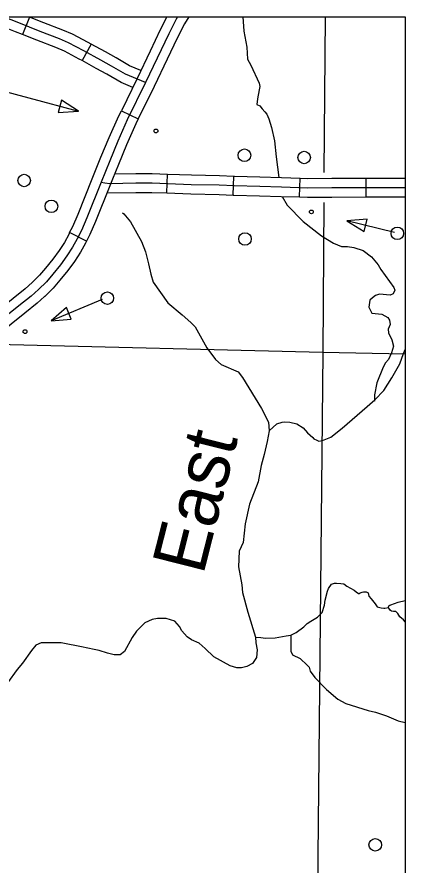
# Model space of a CAD drawing. Extents: x 1382482 to 1385815, y 1168351 to 1170484.
# Drawn here: x 1384816.3 to 1384939.9, y 1169309.6 to 1169579.7 of the extents above; entities that cross this region are included whole.
import ezdxf

# ---------------------------------------------------------------- set-up
doc = ezdxf.new("R2010")
doc.units = 0
for name, color, linetype in [('32', 7, 'Continuous'), ('35', 7, 'Continuous'), ('5', 7, 'Continuous'), ('57', 7, 'Continuous'), ('Default', 7, 'Continuous'), ('R_No Plot', 7, 'Continuous')]:
    doc.layers.add(name, color=color, linetype=linetype)

msp = doc.modelspace()

# ---------------------------------------------------------------- linework, layer by layer
at = {"layer": '32'}
for p, q in [((1384820.26, 1169579.68), (1384818.05, 1169574.1)), ((1384839.91, 1169571.05), (1384837.03, 1169565.79)), ((1384864.05, 1169523.66), (1384864.28, 1169529.65)), ((1384885.14, 1169522.99), (1384885.41, 1169528.99)), ((1384906.29, 1169522.37), (1384906.48, 1169528.36)), ((1384927.5, 1169522.38), (1384927.5, 1169528.38))]:
    msp.add_line(p, q, dxfattribs=at)
for points in [[(1384857.24, 1169558.81), (1384850.81, 1169561.48), (1384846.36, 1169564.05), (1384843.02, 1169565.93), (1384837.54, 1169568.93), (1384832.72, 1169571.48), (1384829.81, 1169572.72), (1384823.72, 1169575.08), (1384816.91, 1169577.78), (1384812.01, 1169579.7)], [(1384820.26, 1169579.68), (1384820.22, 1169579.7)], [(1384839.91, 1169571.05), (1384838.96, 1169571.57), (1384834.01, 1169574.19), (1384830.94, 1169575.5), (1384824.82, 1169577.87), (1384820.26, 1169579.68)], [(1384818.05, 1169574.1), (1384815.82, 1169574.99), (1384810.38, 1169577.11), (1384808.77, 1169577.69), (1384807.88, 1169577.95), (1384806.59, 1169578.16), (1384805.27, 1169578.23), (1384802.64, 1169578.4), (1384799.83, 1169578.53), (1384798.73, 1169578.56)], [(1384837.03, 1169565.79), (1384836.11, 1169566.29), (1384831.43, 1169568.77), (1384828.68, 1169569.94), (1384822.63, 1169572.29), (1384818.05, 1169574.1)], [(1384855.76, 1169562.67), (1384852.14, 1169564.17), (1384847.85, 1169566.65), (1384844.48, 1169568.56), (1384839.91, 1169571.05)], [(1384853.15, 1169557.26), (1384849.48, 1169558.78), (1384844.87, 1169561.44), (1384841.56, 1169563.31), (1384837.03, 1169565.79)], [(1384847.38, 1169529.73), (1384854.15, 1169529.84), (1384859.37, 1169529.84), (1384864.28, 1169529.65)], [(1384864.28, 1169529.65), (1384871.88, 1169529.37), (1384880.84, 1169529.19), (1384885.41, 1169528.99)], [(1384885.41, 1169528.99), (1384885.6, 1169528.98), (1384893.68, 1169528.77), (1384900.58, 1169528.55), (1384906.48, 1169528.36)], [(1384906.48, 1169528.36), (1384908.9, 1169528.29), (1384916.52, 1169528.36), (1384927.5, 1169528.38)], [(1384927.5, 1169528.38), (1384939.88, 1169528.39)], [(1384843.08, 1169527.07), (1384844.24, 1169526.84), (1384845.82, 1169526.71), (1384854.17, 1169526.84), (1384859.31, 1169526.84), (1384871.79, 1169526.37), (1384880.74, 1169526.2), (1384885.5, 1169525.98), (1384893.59, 1169525.77), (1384900.49, 1169525.55), (1384908.86, 1169525.29)], [(1384908.86, 1169525.29), (1384916.53, 1169525.36), (1384939.88, 1169525.39)], [(1384844.96, 1169523.7), (1384854.2, 1169523.84), (1384859.25, 1169523.84), (1384864.05, 1169523.66)], [(1384864.05, 1169523.66), (1384871.71, 1169523.37), (1384880.65, 1169523.2), (1384885.14, 1169522.99)], [(1384885.14, 1169522.99), (1384885.39, 1169522.98), (1384893.5, 1169522.77), (1384900.39, 1169522.55), (1384906.29, 1169522.37)], [(1384906.29, 1169522.37), (1384908.83, 1169522.29), (1384916.55, 1169522.36), (1384927.5, 1169522.38)], [(1384927.5, 1169522.38), (1384939.88, 1169522.39)]]:
    msp.add_lwpolyline(points, dxfattribs=at)
at = {"layer": '35'}
for points in [[(1384888.21, 1169579.7), (1384888.51, 1169575.15), (1384889.47, 1169570.08), (1384889.67, 1169566.29), (1384890.82, 1169564.37), (1384893.44, 1169558.6), (1384893.65, 1169557.56), (1384892.97, 1169554.23), (1384892.77, 1169552.76), (1384892.73, 1169551.77), (1384893.64, 1169551.43), (1384894.41, 1169550.44), (1384895.2, 1169549.45), (1384895.89, 1169548.73), (1384896.46, 1169547.28), (1384897.32, 1169544.51), (1384898.34, 1169540.28), (1384898.81, 1169535.12), (1384899.69, 1169528.58)], [(1384900.75, 1169522.54), (1384902.3, 1169519.79), (1384907.43, 1169514.59), (1384913.32, 1169509.96), (1384917.13, 1169507.64), (1384919.69, 1169506.64), (1384921.54, 1169506.6), (1384923.53, 1169506.26)], [(1384849.95, 1169517.34), (1384850.34, 1169517.01), (1384852.48, 1169514.44), (1384855.97, 1169508.19), (1384857.23, 1169504.88), (1384858.22, 1169501.09), (1384858.88, 1169497.77), (1384859.65, 1169495.22), (1384864.31, 1169488.62), (1384868.95, 1169484.88), (1384871.64, 1169482.44), (1384873, 1169480.97), (1384876.79, 1169474.32), (1384879.57, 1169470.62), (1384881.33, 1169468.99), (1384886.69, 1169466.67), (1384888.09, 1169464.92), (1384894.21, 1169455.05), (1384896.4, 1169450.66), (1384896.56, 1169447.95), (1384896, 1169444.49)], [(1384923.53, 1169506.26), (1384926.57, 1169505.31), (1384929.23, 1169503.35), (1384931.36, 1169500.81), (1384932.16, 1169499.33), (1384936.27, 1169493.57), (1384936.59, 1169492.65), (1384936.06, 1169491.56), (1384935.16, 1169491.09), (1384931.75, 1169491.47), (1384930.46, 1169491.04), (1384929.47, 1169490.22), (1384928.71, 1169489.47), (1384928.38, 1169487.29), (1384929.28, 1169485.39), (1384932.45, 1169485.02), (1384934.45, 1169484), (1384934.94, 1169483.16), (1384935.14, 1169481.8), (1384934.52, 1169480.32), (1384934.64, 1169479.12), (1384935.69, 1169476.93), (1384936.22, 1169474.85), (1384935.56, 1169472.69), (1384934.58, 1169470.64), (1384933.63, 1169469.56), (1384932.88, 1169468.19), (1384930.92, 1169463.22), (1384930.14, 1169459.34), (1384930.16, 1169457.38)], [(1384896.56, 1169447.95), (1384899.03, 1169450.11), (1384900.7, 1169450.64), (1384901.54, 1169450.8), (1384903.22, 1169450.64), (1384905.42, 1169450.11), (1384907.48, 1169448.89), (1384908.85, 1169447.3), (1384910.52, 1169445.77), (1384910.82, 1169445.39), (1384911.74, 1169444.94), (1384912.42, 1169444.63), (1384913.64, 1169444.78), (1384916.22, 1169445.93), (1384919.88, 1169448.74), (1384926.19, 1169454.22), (1384930.3, 1169457.8), (1384933.11, 1169460.77), (1384935.7, 1169464.8), (1384938.21, 1169469.29), (1384939.43, 1169472.56), (1384939.88, 1169473.81)], [(1384896, 1169444.49), (1384895, 1169440.37), (1384894.11, 1169436.89), (1384893.13, 1169431.61), (1384890.3, 1169424.54), (1384888.94, 1169418.26), (1384888.36, 1169412.33), (1384887.11, 1169409.59), (1384886.88, 1169404.57), (1384887.95, 1169398.87), (1384888.17, 1169396.39), (1384889.87, 1169390.17), (1384892.27, 1169382.24), (1384892.37, 1169380.35), (1384892.78, 1169378.19), (1384892.56, 1169375.71), (1384891.3, 1169373.8), (1384889.51, 1169372.85), (1384887.8, 1169372.39), (1384886.33, 1169372.43), (1384884.17, 1169373.11), (1384878.99, 1169375.92), (1384876.27, 1169378.56), (1384874.27, 1169380.27), (1384871.88, 1169381.36), (1384870.45, 1169382.35), (1384868.8, 1169384.18), (1384868.1, 1169385.61), (1384866.52, 1169387.29), (1384863.86, 1169388.16), (1384861.02, 1169388.18), (1384859.38, 1169387.81), (1384856.98, 1169386.77), (1384854.37, 1169384.07), (1384853, 1169382.04), (1384850.52, 1169377.58), (1384849.18, 1169376.53), (1384847.25, 1169376.61), (1384845.09, 1169377.06), (1384842.5, 1169377.97), (1384840.85, 1169378.25), (1384836.86, 1169379.08), (1384834.7, 1169379.5), (1384832.99, 1169379.9), (1384830.34, 1169380.41), (1384823.96, 1169380.41), (1384822.32, 1169379.7), (1384820.95, 1169377.99), (1384818.04, 1169373.94), (1384816.33, 1169371.94), (1384813.31, 1169367.67)], [(1384915.46, 1169397.68), (1384916.49, 1169399.1), (1384917.4, 1169399.44), (1384918.08, 1169399.44), (1384919.45, 1169399.27), (1384920.42, 1169399.15), (1384921.39, 1169398.47), (1384923.73, 1169397.21), (1384924.36, 1169396.64), (1384925.04, 1169396.13), (1384925.27, 1169396.13), (1384925.55, 1169396.36), (1384926.24, 1169396.53), (1384926.64, 1169396.64), (1384927.55, 1169396.64), (1384928.12, 1169396.3), (1384928.4, 1169395.28), (1384929.09, 1169394.42), (1384930.34, 1169392.77), (1384931.03, 1169391.85), (1384932.28, 1169391.57), (1384933.08, 1169391.45), (1384933.48, 1169391.45), (1384934.62, 1169391.68)], [(1384892.27, 1169382.24), (1384893.98, 1169382.07), (1384895.49, 1169381.84), (1384898.57, 1169382.02), (1384901.99, 1169382.59), (1384903.56, 1169382.87), (1384905.19, 1169383.73), (1384907.7, 1169385.5), (1384908.72, 1169386.52), (1384909.92, 1169387.26), (1384912.03, 1169388.58), (1384913.46, 1169390), (1384914.2, 1169392.4), (1384914.43, 1169394), (1384915.17, 1169396.85), (1384915.46, 1169397.68)], [(1384939.88, 1169387.12), (1384939.38, 1169387.76), (1384938.24, 1169388.68), (1384937.55, 1169389.76), (1384936.98, 1169390.33), (1384936.18, 1169390.39), (1384935.61, 1169390.44), (1384935.27, 1169390.73), (1384934.76, 1169391.41), (1384934.62, 1169391.68), (1384934.73, 1169392.14), (1384935.08, 1169392.38), (1384935.4, 1169392.49), (1384937.68, 1169393.34), (1384939.88, 1169393.91)], [(1384903.56, 1169382.87), (1384903.5, 1169381.73), (1384903.5, 1169379.33), (1384903.56, 1169377.73), (1384904.07, 1169376.59), (1384906.47, 1169375.39), (1384908.75, 1169373.23), (1384909.37, 1169372.6), (1384909.65, 1169371.35), (1384911.14, 1169369.36), (1384914.87, 1169365.55), (1384918.52, 1169362.5), (1384921.04, 1169361.12), (1384928.19, 1169358.85), (1384930.5, 1169358.3), (1384933.98, 1169357.17), (1384937.65, 1169355.56), (1384939.88, 1169354.98)]]:
    msp.add_lwpolyline(points, dxfattribs=at)
at = {"layer": '5'}
for points in [[(1384914.41, 1169579.7), (1384914.07, 1169530.19)], [(1384914, 1169520.62), (1384913.68, 1169472.9)], [(1384809.66, 1169475.5), (1384913.68, 1169472.9)], [(1384913.68, 1169472.9), (1384911.88, 1169290.87)], [(1384913.68, 1169472.9), (1384939.88, 1169472.42)]]:
    msp.add_lwpolyline(points, dxfattribs=at)
at = {"layer": '57'}
msp.add_lwpolyline([(1384804.15, 1169558.21), (1384835.89, 1169549.68)], dxfattribs=at)
msp.add_lwpolyline([(1384830.51, 1169553.24), (1384829.45, 1169549.3), (1384835.89, 1169549.68)], close=True, dxfattribs=at)
msp.add_circle((1384860.57, 1169543.4), 0.6, dxfattribs=at)
at = {"layer": 'Default'}
for p, q in [((1384849.54, 1169549.84), (1384854.93, 1169547.21)), ((1384838.42, 1169508.29), (1384833.07, 1169511.01)), ((1384838.42, 1169508.29), (1384838.42, 1169508.29))]:
    msp.add_line(p, q, dxfattribs=at)
for points in [[(1384867.43, 1169579.7), (1384867, 1169579.03), (1384864.61, 1169574.3), (1384857.24, 1169558.81)], [(1384863.98, 1169579.7), (1384861.92, 1169575.62), (1384858.69, 1169568.84)], [(1384870.99, 1169579.7), (1384869.61, 1169577.54), (1384867.3, 1169572.98), (1384864.11, 1169566.26)], [(1384858.69, 1169568.84), (1384854.54, 1169560.11), (1384849.54, 1169549.84)], [(1384864.11, 1169566.26), (1384859.95, 1169557.51), (1384854.93, 1169547.21)], [(1384857.24, 1169558.81), (1384851.44, 1169546.89), (1384848.46, 1169540.16), (1384845.82, 1169533.9), (1384843.08, 1169527.07), (1384838.58, 1169515.76), (1384836.8, 1169511.71), (1384835.43, 1169509.03), (1384833.99, 1169506.35), (1384832.2, 1169503.58), (1384830.11, 1169500.77), (1384827.68, 1169497.74), (1384825.66, 1169495.38), (1384823.15, 1169492.91), (1384820.81, 1169490.82), (1384816.93, 1169487.67), (1384808.12, 1169480.69)], [(1384841.12, 1169530.24), (1384843.05, 1169535.04), (1384845.71, 1169541.35), (1384848.72, 1169548.16), (1384849.54, 1169549.84)], [(1384854.93, 1169547.21), (1384854.16, 1169545.63), (1384851.22, 1169538.97), (1384848.6, 1169532.76), (1384846.69, 1169528)], [(1384833.07, 1169511.01), (1384834.08, 1169513), (1384835.82, 1169516.92), (1384840.29, 1169528.18), (1384841.12, 1169530.24)], [(1384846.69, 1169528), (1384845.86, 1169525.95), (1384841.35, 1169514.6), (1384839.51, 1169510.43), (1384838.42, 1169508.29)], [(1384936.53, 1169511.03), (1384921.38, 1169514.78)], [(1384833.07, 1169511.01), (1384832.78, 1169510.42), (1384831.4, 1169507.88), (1384829.73, 1169505.29), (1384827.74, 1169502.6), (1384825.37, 1169499.66), (1384823.47, 1169497.43), (1384821.1, 1169495.1), (1384821.1, 1169495.1)], [(1384838.42, 1169508.29), (1384838.09, 1169507.64), (1384836.57, 1169504.82), (1384834.66, 1169501.87), (1384832.49, 1169498.94), (1384829.99, 1169495.83), (1384827.86, 1169493.33), (1384825.2, 1169490.72), (1384825.1, 1169490.63)], [(1384821.1, 1169495.1), (1384818.86, 1169493.11), (1384815.06, 1169490.01), (1384806.25, 1169483.03), (1384804.82, 1169481.88)], [(1384825.09, 1169490.63), (1384822.75, 1169488.54), (1384818.81, 1169485.33), (1384810, 1169478.35), (1384808.6, 1169477.22)], [(1384843.38, 1169489.68), (1384827.17, 1169482.98)]]:
    msp.add_lwpolyline(points, dxfattribs=at)
for points in [[(1384926.83, 1169511.33), (1384927.81, 1169515.29), (1384921.38, 1169514.78)], [(1384833.6, 1169483.44), (1384832.05, 1169487.21), (1384827.17, 1169482.98)]]:
    msp.add_lwpolyline(points, close=True, dxfattribs=at)
for centre, radius in [((1384888.74, 1169535.66), 2), ((1384907.76, 1169534.93), 2), ((1384818.6, 1169527.61), 2), ((1384827.27, 1169519.4), 2), ((1384910.05, 1169517.62), 0.6), ((1384937.42, 1169510.78), 2), ((1384888.9, 1169509), 2), ((1384845.09, 1169490.16), 2), ((1384818.86, 1169479.5), 0.6), ((1384930.4, 1169316.08), 2)]:
    msp.add_circle(centre, radius, dxfattribs=at)
at = {"layer": 'R_No Plot'}
msp.add_lwpolyline([(1383432.46, 1169579.7), (1384939.88, 1169579.7), (1384939.88, 1168702.36), (1383432.46, 1168702.36)], close=True, dxfattribs=at)

# ---------------------------------------------------------------- texts
at = {"layer": '35'}
msp.add_text('East', height=16.896, rotation=75.7977, dxfattribs=at).set_placement((1384875.57, 1169401.67))

doc.saveas('drawing.dxf')
